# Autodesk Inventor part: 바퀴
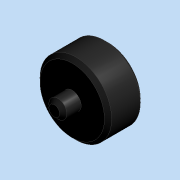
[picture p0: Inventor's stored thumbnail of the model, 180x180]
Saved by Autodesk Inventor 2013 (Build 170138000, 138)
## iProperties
Company: 한국ATC센터
Created: 2015-05
Part Number: 바퀴
Document SubType Name: 모델링
Designer: KYOUNG IL JANG
Vendor: CBT Solutions
Material: 일반
Author: KYOUNG IL JANG
Comments: 파생
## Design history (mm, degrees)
derived "바퀴.ipt"
node "솔리드1"
node "솔리드 본체"
node "곡면 본체"
feature "솔리드1::바퀴.ipt" dims "d0" = 10
tag "피쳐 태그1"
